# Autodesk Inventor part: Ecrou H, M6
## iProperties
Shininess: 64.0
Length Units: 11269
Angle Units: 11279
Time Units: 11290
Mass Units: 11283
Length Display Precision: 3
Angle Display Precision: 2
Compacted: True
Part Number: Ecrou H, M6
Document SubType Name: Modeling
Created: 2006-01
Material: Par défaut
Designer: Fricot
Density: 0.0
Volumn: 0.0
Area: 0.0
PropertySet Name: Model Information
Control State: 0
Master: False
Checked Out: False
Author: Fricot
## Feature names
1. Base1
